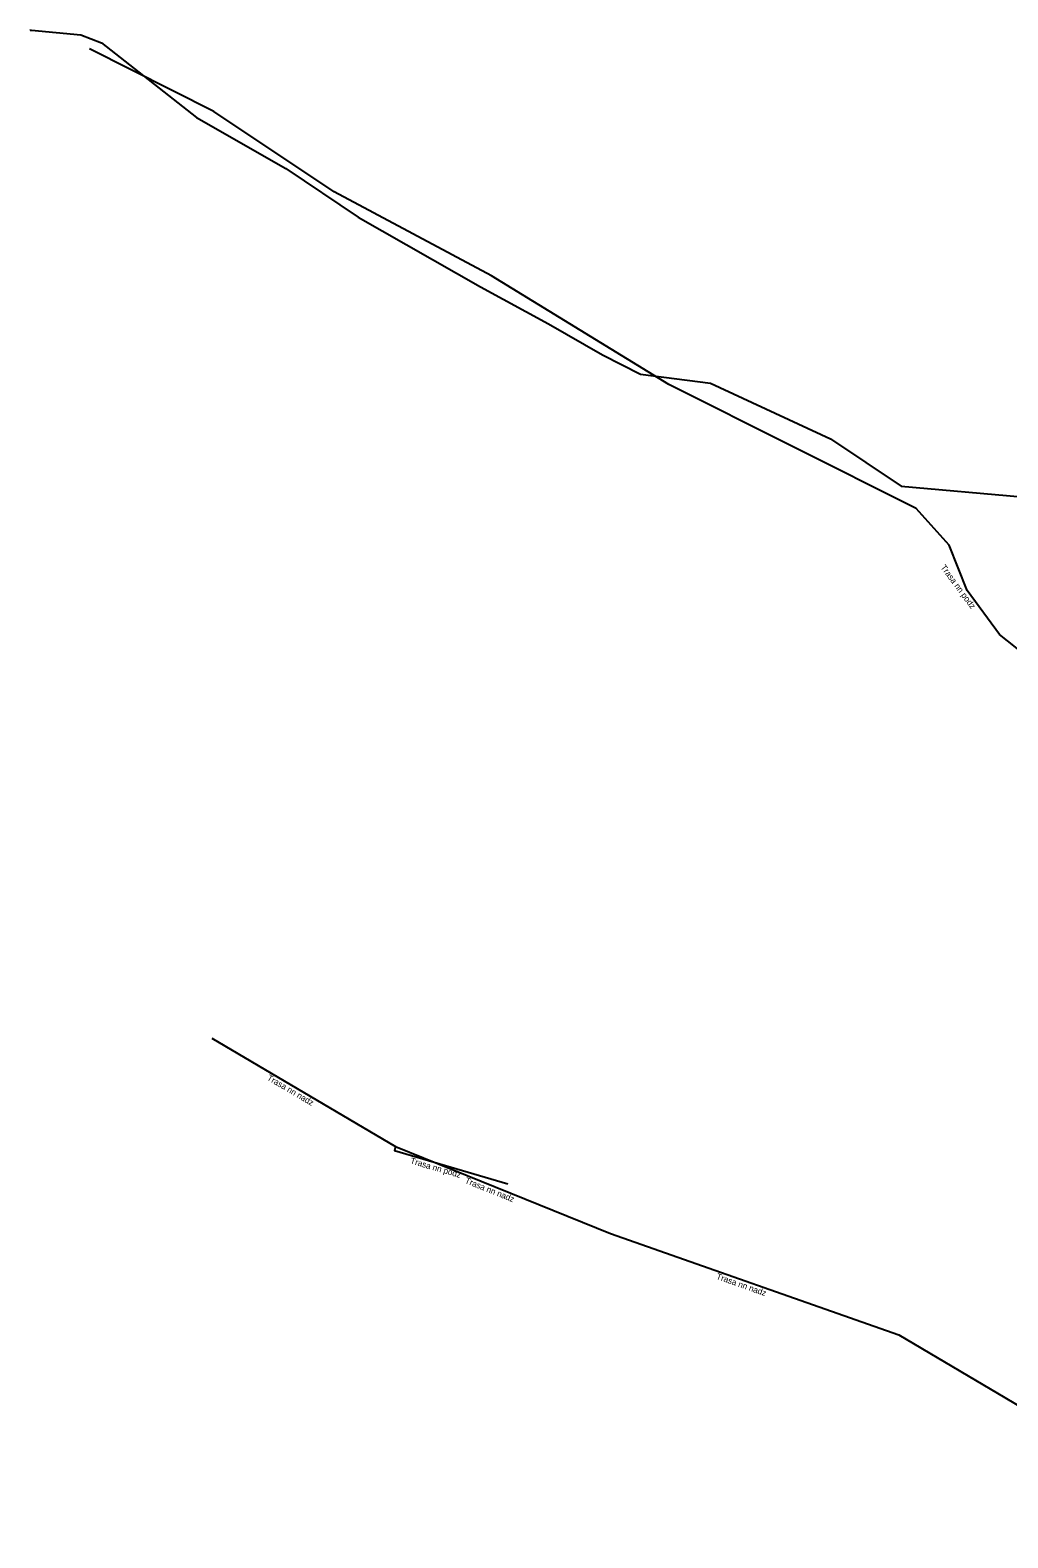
# Model space of a CAD drawing. Extents: x -682605 to -681948, y -1059884 to -1059661.
# Drawn here: x -682604.7 to -682524.8, y -1059852.5 to -1059729.3 of the extents above; entities that cross this region are included whole.
import ezdxf

# ---------------------------------------------------------------- set-up
doc = ezdxf.new("R2010")
doc.units = 0
for name, color, linetype in [('Popiskový text - Ostatní atributy Trasy', 7, 'Continuous'), ('Spojnice NN', 7, 'Continuous'), ('Spojnice VN', 7, 'Continuous')]:
    doc.layers.add(name, color=color, linetype=linetype)

msp = doc.modelspace()

# ---------------------------------------------------------------- linework, layer by layer
at = {"layer": 'Spojnice NN'}
for points in [[(-682447.96, -1059790.21), (-682459.73, -1059794.22), (-682460.78, -1059794.04), (-682462.86, -1059792.75), (-682471.05, -1059793.41), (-682474.96, -1059793.4), (-682481.35, -1059793.46), (-682493.93, -1059791.42), (-682506.56, -1059788.09), (-682521.99, -1059781.45), (-682525.52, -1059778.64), (-682528.18, -1059775.05), (-682529.63, -1059771.35), (-682532.33, -1059768.34), (-682552.54, -1059758.22), (-682567.03, -1059749.33), (-682579.9, -1059742.47), (-682589.71, -1059735.91), (-682599.88, -1059730.78)], [(-682589.89, -1059811.62), (-682574.87, -1059820.47)], [(-682574.87, -1059820.47), (-682574.96, -1059820.81), (-682565.71, -1059823.52)], [(-682574.87, -1059820.47), (-682557.3, -1059827.58)], [(-682557.3, -1059827.58), (-682533.75, -1059835.88)], [(-682533.75, -1059835.88), (-682505.69, -1059852.46)]]:
    msp.add_lwpolyline(points, dxfattribs=at)
at = {"layer": 'Spojnice VN'}
msp.add_lwpolyline([(-682604.72, -1059729.27), (-682604.72, -1059729.27), (-682604.62, -1059729.27), (-682600.59, -1059729.66), (-682598.9, -1059730.29), (-682591.14, -1059736.39), (-682583.84, -1059740.58), (-682577.93, -1059744.56), (-682567.92, -1059750.23), (-682562.37, -1059753.27), (-682557.96, -1059755.8), (-682554.87, -1059757.37), (-682549.15, -1059758.11), (-682539.34, -1059762.65), (-682533.57, -1059766.53), (-682523.72, -1059767.39)], dxfattribs=at)

# ---------------------------------------------------------------- texts
at = {"layer": 'Popiskový text - Ostatní atributy Trasy'}
for s, rotation, p in [('Trasa nn podz', 306.4616, (-682530.37, -1059773.17)), ('Trasa nn nadz', 329.4943, (-682585.42, -1059815.01)), ('Trasa nn podz', 343.697, (-682573.71, -1059821.86)), ('Trasa nn nadz', 337.9718, (-682569.25, -1059823.45)), ('Trasa nn nadz', 340.5839, (-682548.71, -1059831.3))]:
    msp.add_text(s, height=0.5, rotation=rotation, dxfattribs=at).set_placement(p)

doc.saveas('drawing.dxf')
